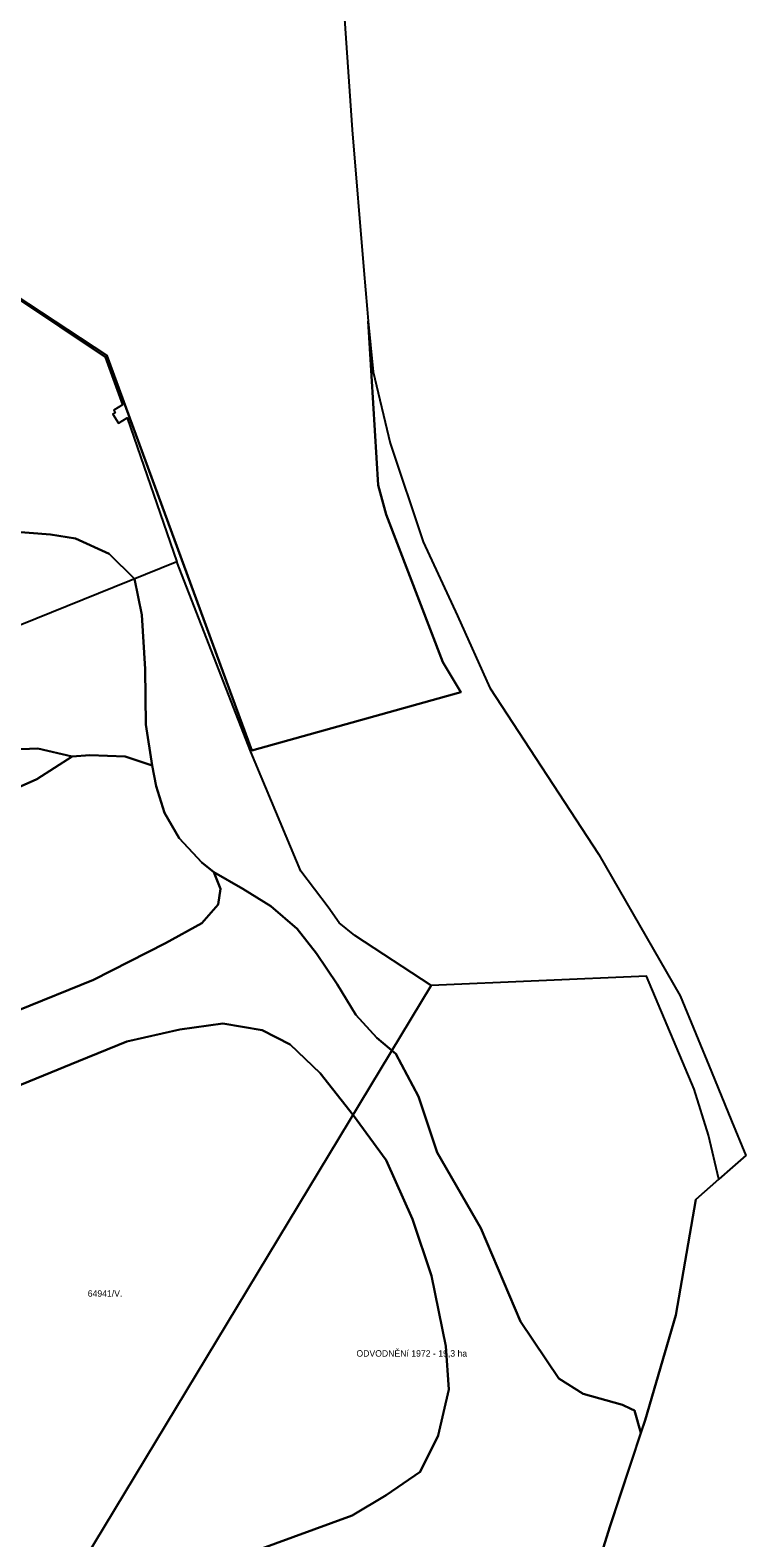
# Model space of a CAD drawing. Extents: x -521621 to -516761, y -1190184 to -1184927.
# Drawn here: x -517203 to -516761, y -1186934 to -1186003 of the extents above; entities that cross this region are included whole.
import ezdxf

# ---------------------------------------------------------------- set-up
doc = ezdxf.new("R2010")
doc.units = 0
doc.layers.add('BPEJ_s', color=7, linetype='Continuous')
doc.layers.add('odvodneni_s', color=7, linetype='Continuous')

msp = doc.modelspace()

# ---------------------------------------------------------------- linework, layer by layer
at = {"layer": 'BPEJ_s'}
for points in [[(-517010.1, -1185971.5), (-517003.7, -1186064.07), (-516996.45, -1186150.98), (-516994.45, -1186174.89), (-516993.72, -1186182.37), (-516987.52, -1186283.72), (-516982.63, -1186301.86), (-516947.67, -1186392.9), (-516936.44, -1186411.43), (-517065.71, -1186447.49), (-517155.08, -1186203.57), (-517219.62, -1186161.17), (-517243.4, -1186145.18), (-517307.11, -1186098.35), (-517314.39, -1186081.29), (-517323.17, -1186060.77), (-517357.41, -1185980.53)], [(-517219.62, -1186161.17), (-517155.08, -1186203.57), (-517065.71, -1186447.49), (-516936.44, -1186411.43), (-516947.67, -1186392.9), (-516982.63, -1186301.86), (-516987.52, -1186283.72), (-516993.72, -1186182.37), (-516990.65, -1186213.57), (-516980.18, -1186257.64), (-516959.79, -1186318.69), (-516938.61, -1186364.42), (-516918.56, -1186408.79), (-516851.25, -1186511.77), (-516801.06, -1186599.08), (-516781.74, -1186646.08), (-516769.31, -1186676.3), (-516760.51, -1186697.7), (-516768.82, -1186705.01), (-516777.29, -1186712.47), (-516791.41, -1186724.89), (-516803.7, -1186796.3), (-516822.77, -1186861.25), (-516825.38, -1186869.15), (-516829.21, -1186855.22), (-516831.48, -1186854.19), (-516836.66, -1186851.83), (-516861.06, -1186845.05), (-516875.97, -1186835.55), (-516899.69, -1186800.29), (-516924.09, -1186742.65), (-516951.2, -1186695.86), (-516962.72, -1186661.28), (-516976.61, -1186635), (-516988.47, -1186625.17), (-517001.35, -1186610.93), (-517012.87, -1186591.94), (-517025.74, -1186572.95), (-517037.6, -1186557.69), (-517053.87, -1186543.79), (-517071.15, -1186532.94), (-517089.11, -1186522.77), (-517096.56, -1186516.67), (-517110.46, -1186501.75), (-517119.6, -1186486.15), (-517124.69, -1186469.54), (-517127.1, -1186456.8), (-517131.06, -1186431.55), (-517131.56, -1186397.39), (-517133.54, -1186363.73), (-517137.99, -1186341.45), (-517153.82, -1186326.1), (-517174.6, -1186316.7), (-517189.94, -1186314.22), (-517213.69, -1186312.24)], [(-517213.69, -1186312.24), (-517189.94, -1186314.22), (-517174.6, -1186316.7), (-517153.82, -1186326.1), (-517137.99, -1186341.45), (-517133.54, -1186363.73), (-517131.56, -1186397.39), (-517131.06, -1186431.55), (-517127.1, -1186456.8), (-517143.93, -1186451.36), (-517165.7, -1186450.36), (-517176.58, -1186451.36), (-517197.86, -1186446.41), (-517224.08, -1186447.4)], [(-517224.08, -1186447.4), (-517197.86, -1186446.41), (-517176.58, -1186451.36), (-517198.35, -1186465.22), (-517221.6, -1186475.61)], [(-517221.6, -1186475.61), (-517198.35, -1186465.22), (-517176.58, -1186451.36), (-517165.7, -1186450.36), (-517143.93, -1186451.36), (-517127.1, -1186456.8), (-517124.69, -1186469.54), (-517119.6, -1186486.15), (-517110.46, -1186501.75), (-517096.56, -1186516.67), (-517089.11, -1186522.77), (-517085.04, -1186532.94), (-517086.4, -1186542.78), (-517096.56, -1186554.3), (-517118.93, -1186566.51), (-517163.32, -1186589.23), (-517210.08, -1186608.21)], [(-517210.08, -1186608.21), (-517163.32, -1186589.23), (-517118.93, -1186566.51), (-517096.56, -1186554.3), (-517086.4, -1186542.78), (-517085.04, -1186532.94), (-517089.11, -1186522.77), (-517071.15, -1186532.94), (-517053.87, -1186543.79), (-517037.6, -1186557.69), (-517025.74, -1186572.95), (-517012.87, -1186591.94), (-517001.35, -1186610.93), (-516988.47, -1186625.17), (-516976.61, -1186635), (-516962.72, -1186661.28), (-516951.2, -1186695.86), (-516924.09, -1186742.65), (-516899.69, -1186800.29), (-516875.97, -1186835.55), (-516861.06, -1186845.05), (-516836.66, -1186851.83), (-516831.48, -1186854.19), (-516829.21, -1186855.22), (-516825.38, -1186869.15), (-516844.56, -1186927.14), (-516850.39, -1186946.24)], [(-517063.94, -1186942.21), (-517003.71, -1186920.26), (-516982.7, -1186907.64), (-516961.69, -1186893.16), (-516950.49, -1186870.74), (-516943.95, -1186842.24), (-516945.82, -1186815.61), (-516954.69, -1186772.16), (-516966.36, -1186737.13), (-516982.7, -1186700.69), (-517002.78, -1186673.12), (-517023.32, -1186646.96), (-517042, -1186629.21), (-517059.27, -1186620.33), (-517083.55, -1186616.13), (-517110.16, -1186619.87), (-517142.84, -1186627.34), (-517172.72, -1186639.49), (-517220.35, -1186659.11)], [(-517220.35, -1186659.11), (-517172.72, -1186639.49), (-517142.84, -1186627.34), (-517110.16, -1186619.87), (-517083.55, -1186616.13), (-517059.27, -1186620.33), (-517042, -1186629.21), (-517023.32, -1186646.96), (-517002.78, -1186673.12), (-516982.7, -1186700.69), (-516966.36, -1186737.13), (-516954.69, -1186772.16), (-516945.82, -1186815.61), (-516943.95, -1186842.24), (-516950.49, -1186870.74), (-516961.69, -1186893.16), (-516982.7, -1186907.64), (-517003.71, -1186920.26), (-517063.94, -1186942.21)]]:
    msp.add_lwpolyline(points, dxfattribs=at)
at = {"layer": 'odvodneni_s'}
for points in [[(-517240.3, -1186148.46), (-517156.28, -1186204.57), (-517145.46, -1186233.96), (-517150.84, -1186237.35), (-517150.08, -1186238.88), (-517151.51, -1186239.83), (-517147.98, -1186245.42), (-517142.59, -1186242.13), (-517112.03, -1186330.95), (-517218.36, -1186374.05)], [(-517175.45, -1186958.22), (-516954.83, -1186592.8), (-517002.05, -1186561.79), (-517011.76, -1186553.99), (-517018.44, -1186544.45), (-517035.44, -1186522.2), (-517066.22, -1186448.33), (-517112.03, -1186330.95), (-517218.36, -1186374.05)]]:
    msp.add_lwpolyline(points, dxfattribs=at)
msp.add_lwpolyline([(-516954.83, -1186592.8), (-517175.45, -1186958.22), (-517134.87, -1186982.42), (-516976.29, -1187062.17), (-516877.08, -1186998.25), (-516871.88, -1187016.23), (-516856.6, -1186966.47), (-516850.39, -1186946.24), (-516844.56, -1186927.14), (-516822.77, -1186861.25), (-516803.7, -1186796.3), (-516791.41, -1186724.89), (-516777.29, -1186712.47), (-516783.52, -1186685.16), (-516792.51, -1186656.77), (-516821.91, -1186586.88)], close=True, dxfattribs=at)

# ---------------------------------------------------------------- texts
at = {"layer": 'BPEJ_s'}
msp.add_text('64941/V.', height=4, dxfattribs=at).set_placement((-517166.97, -1186785.01))
at = {"layer": 'odvodneni_s'}
msp.add_text('ODVODNĚNí 1972 - 19,3 ha', height=4, dxfattribs=at).set_placement((-517001.01, -1186822.03))

doc.saveas('drawing.dxf')
